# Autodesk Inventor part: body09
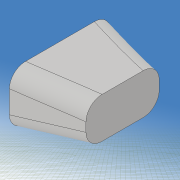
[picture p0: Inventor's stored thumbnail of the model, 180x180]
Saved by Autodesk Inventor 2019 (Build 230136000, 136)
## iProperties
Created: 2020-12
Part Number: body09
Material: 一般
Document SubType Name: Modeling
Designer: kikut
Density: 1 g/cm^3
Appearance: 既定
Mass: 87.6477 g
Surface Area: 156.124 cm^2
Volume: 87.6477 cm^3
Author: kikut
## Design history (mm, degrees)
sketch "スケッチ1"
  geometry: L1 (-100, -20)-(100, -20); L2 (100, -20)-(100, 20); L3 (100, 20)-(-100, 20); L4 (-100, 20)-(-100, -20); L5 (-100, -20)-(100, 20); L6 (100, -20)-(-100, 20); 1 further point
  constraints: 12 end point, 2 midpoint, 2 parallel, 1 horizontal, 1 perpendicular
  dimensions: "d0" = 40 distance of L3.end L1.start; "d1" = 200 distance of L2.end L3.end
extrude "押し出し1" new body sketch "スケッチ1" stored distance "d2" = 60; taper "d3" = 0 deg
sketch "スケッチ2"
  geometry: L1 (0, -60)-(0, 0) reference; L2 (200, -60)-(200, 0) reference; L3 (0, 0)-(200, 0) reference; L4 (200, -60)-(0, -60) reference; L5 (0, -26)-(0, -32); L6 (194, -10)-(194, -13); L7 (194, -13)-(174, -33); L8 (174, -33)-(200, -58); L9 (-20, 20)-(220, 20); L10 (220, 20)-(220, -100); L11 (220, -100)-(-20, -100); L12 (-20, -100)-(-20, 20); 12 further points
  constraints: 16 end point, 4 point on line, 2 parallel, 2 vertical, 1 horizontal, 1 perpendicular, 14 other
  dimensions: "d4" = 32 distance from line of point (32, -12) L1; "d5" = 50 horizontal distance of point (32, -12) point (82, -11); "d6" = 50 horizontal distance of point (132, -17) point (82, -11); "d7" = 12 distance from line of point (32, -12) L3; "d8" = 11 distance from line of point (82, -11) L3; "d10" = 17 distance from line of point (132, -17) L3; "d11" = 26 distance from line of L5.start L3; "d12" = 0 distance from line of point (200, -60) L4; "d13" = 28 distance from line of L5.end L4; "d14" = 12 distance from line of point (28, -48) L4; "d15" = 10 distance from line of point (80, -50) L4; "d16" = 16 distance from line of point (130, -44) L4; "d17" = 28 distance from line of point (28, -48) L1; "d19" = 50 horizontal distance of point (130, -44) point (80, -50); "d20" = 80 distance from line of point (80, -50) L1; "d21" = 6 distance from line of L6.start L2; "d22" = 36 distance from line of point (164, -24) L2; "d23" = 24 distance from line of point (176, -20) L2; "d24" = 10 distance from line of L6.start L3; "d25" = 20 distance from line of point (176, -20) L3; "d26" = 24 distance from line of point (164, -24) L3; "d27" = 40 distance from line of point (160, -40) L2; "d28" = 25 distance from line of point (175, -47.5) L2; "d29" = 12.5 distance from line of point (175, -47.5) L4; "d30" = 20 distance from line of L4 point (160, -40); "d31" = 3 distance of L6.start L6.end; "d32" = 33 distance from line of L7.end L3; "d33" = 26 distance from line of L7.end L2; "d34" = 2 distance of L8.end L2.start; "d35" = 120 distance of L11.end L9.start; "d36" = 240 distance of L10.end L11.end; "d37" = 20 distance between parallel lines of L1 L12; "d38" = 20 distance between parallel lines of L3 L9
extrude "押し出し2" cut sketch "スケッチ2" extent not by distance; stored distance "d39" = 0.02; taper "d40" = 0 deg
sketch "スケッチ8"
  geometry: L1 (-100, -20)-(-100, 20) reference; L2 (100, 20)-(100, -20) reference; L3 (-142.805, 0)-(142.831, 0) reference; L4 (110, 30)-(-110, 30); L5 (-110, 30)-(-110, -30); L6 (-110, -30)-(110, -30); L7 (110, -30)-(110, 30); L8 (110, 30)-(-110, -30); L9 (-110, 30)-(110, -30); L10 (-100, -2)-(-100, 2); L11 (100, -3)-(100, 3); 7 further points
  constraints: 16 end point, 4 point on line, 2 midpoint, 2 parallel, 2 perpendicular, 1 collinear, 1 horizontal, 10 other
  dimensions: "d93" = 2 vertical distance of point (0, 0) L10.end; "d94" = 2 vertical distance of L10.start point (0, 0); "d95" = 35 distance from line of point (-65, -10) L1; "d96" = 0 horizontal distance of point (-65, 10) point (-65, -10); "d97" = 10 vertical distance of point (0, 0) point (-65, -10); "d98" = 10 vertical distance of point (-65, 10) point (0, 0); "d99" = 100 distance from line of point (0, -10) L1; "d100" = 0 horizontal distance of point (0, 10) point (0, -10); "d101" = 10 distance of point (0, -10) point (0, 0); "d102" = 10 distance of point (0, 0) point (0, 10); "d103" = 160 distance from line of point (60, -4) L1; "d104" = 0 horizontal distance of point (60, 4) point (60, -4); "d105" = 4 distance from line of L3 point (60, -4); "d106" = 4 distance from line of L3 point (60, 4); "d107" = 3 distance from line of L11.start L3; "d108" = 3 distance from line of L11.end L3; "d109" = 220 distance of L5.end L6.end; "d110" = 60 distance of L4.end L5.end
extrude "押し出し6" cut sketch "スケッチ8" extent not by distance; stored distance "d111" = 10; taper "d112" = 0 deg
sketch "スケッチ9" dims "d113" = 20, "d114" = 12
  geometry: L1 (-29, -18)-(21, -18); L2 (21, -18)-(21, 22); L3 (21, 22)-(-29, 22); L4 (-29, 22)-(-29, -18); L5 (-29, -18)-(21, 22); L6 (21, -18)-(-29, 22); 2 further points; 1 other entity
  constraints: 12 end point, 2 midpoint, 2 parallel, 1 coincident, 1 horizontal, 1 perpendicular, 2 other
  dimensions: "d115" = 50 distance of L2.end L3.end; "d116" = 40 distance of L1.end L2.end
extrude "押し出し7" cut sketch "スケッチ9" distance "d117" = 150; taper "d118" = 0 deg
fillet "フィレット4" dims "d119" = 4
fillet "フィレット5" dims "d120" = 4
fillet "フィレット6" dims "d121" = 2
node "作業平面2"
sketch "スケッチ10"
  geometry: L1 (0, -41.439)-(0, 38.458) reference; L2 (141.833, 0)-(-140.631, 0) reference; L3 (82.55, 12.983)-(81.45, -4.983); A1 r 9 centre (82, 4) between (82.55, 12.983) and (81.45, -4.983); 1 further point
  constraints: 2 end point, 2 point on circle, 1 centre point
  dimensions: "d123" = 82 distance from line of L1 A1.centre; "d124" = 4 distance from line of L2 A1.centre; "d125" = 9 radius of A1; "d126" = 180 deg dimension on A1.centre L3.end L3.start; "d127" = 90 deg dimension on L3.end point (0, 0) A1.centre
revolve "回転1" sketch "スケッチ10" stored, may be unused: angle "d128" = 90 deg
mirror "ミラー1"
sketch "スケッチ11"
  geometry: L1 (-35, 30)-(-50, 30); L2 (-50, 30)-(-50, -30); L3 (-50, -30)-(-35, -30); L4 (-35, -30)-(-35, 30); L5 (0, -40.648)-(0, 34.486) reference; L6 (140.69, 0)-(-139.196, 0) reference; L7 (120, 53.792)-(-120, 53.792); L8 (-120, 53.792)-(-120, -46.208); L9 (-120, -46.208)-(120, -46.208); L10 (120, -46.208)-(120, 53.792); 1 further point
  constraints: 16 end point, 4 parallel, 2 horizontal, 2 perpendicular, 2 other
  dimensions: "d130" = 15 distance of L1.start L1.end; "d131" = 60 distance of L3.end L1.start; "d132" = 100 distance of L9.end L7.start; "d133" = 240 distance of L7.start L7.end; "d137" = 50 distance between parallel lines of L2 L5
extrude "押し出し8" cut sketch "スケッチ11" stored distance "d134" = 40; taper "d135" = 0 deg
node "ソリッド1"
other parameters: "d122" = -1
